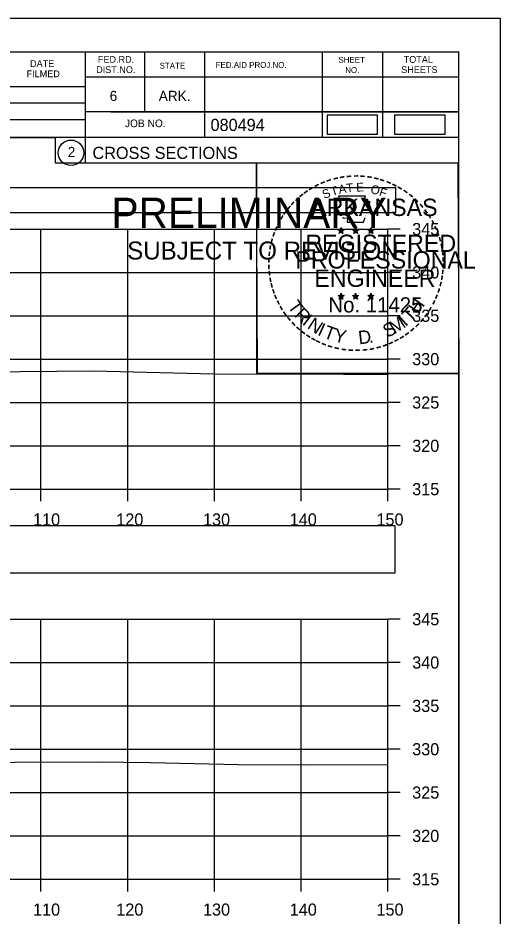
# Model space of a CAD drawing. Extents: x 1376273 to 1384221, y 378927 to 384592.
# Drawn here: x 1380299 to 1380354.6, y 384275 to 384378.6 of the extents above; entities that cross this region are included whole.
import ezdxf

# ---------------------------------------------------------------- set-up
doc = ezdxf.new("R2010")
doc.units = 0
for name, color, linetype in [('R_Axis', 7, 'Continuous'), ('R_Axis Annot', 7, 'Continuous'), ('R_Border', 7, 'Continuous'), ('R_Border PE', 7, 'Continuous'), ('R_Border Prem', 7, 'Continuous'), ('R_Drive', 7, 'Continuous'), ('R_Exist Surface', 7, 'Continuous'), ('R_Grid', 7, 'Continuous'), ('R_No Plot', 7, 'Continuous')]:
    doc.layers.add(name, color=color, linetype=linetype)

msp = doc.modelspace()

# ---------------------------------------------------------------- linework, layer by layer
at = {"layer": 'R_Axis'}
for p, q in [((1380341.66, 384324.24), (1380341.66, 384354.24)), ((1380343.06, 384354.24), (1380341.66, 384354.24)), ((1380343.06, 384349.24), (1380341.66, 384349.24)), ((1380343.06, 384344.24), (1380341.66, 384344.24)), ((1380343.06, 384339.24), (1380341.66, 384339.24)), ((1380343.06, 384334.24), (1380341.66, 384334.24)), ((1380343.06, 384329.24), (1380341.66, 384329.24)), ((1380041.66, 384324.24), (1380341.66, 384324.24)), ((1380301.66, 384322.84), (1380301.66, 384324.24)), ((1380311.66, 384322.84), (1380311.66, 384324.24)), ((1380321.66, 384322.84), (1380321.66, 384324.24)), ((1380331.66, 384322.84), (1380331.66, 384324.24)), ((1380341.66, 384322.84), (1380341.66, 384324.24)), ((1380343.06, 384324.24), (1380341.66, 384324.24)), ((1380341.66, 384279.24), (1380341.66, 384309.24)), ((1380343.06, 384309.24), (1380341.66, 384309.24)), ((1380343.06, 384304.24), (1380341.66, 384304.24)), ((1380343.06, 384299.24), (1380341.66, 384299.24)), ((1380343.06, 384294.24), (1380341.66, 384294.24)), ((1380343.06, 384289.24), (1380341.66, 384289.24)), ((1380343.06, 384284.24), (1380341.66, 384284.24)), ((1380041.66, 384279.24), (1380341.66, 384279.24)), ((1380301.66, 384277.84), (1380301.66, 384279.24)), ((1380311.66, 384277.84), (1380311.66, 384279.24)), ((1380321.66, 384277.84), (1380321.66, 384279.24)), ((1380331.66, 384277.84), (1380331.66, 384279.24)), ((1380341.66, 384277.84), (1380341.66, 384279.24)), ((1380343.06, 384279.24), (1380341.66, 384279.24))]:
    msp.add_line(p, q, dxfattribs=at)
at = {"layer": 'R_Axis Annot'}
for points in [[(1380040.77, 384356.17), (1380342.57, 384356.17), (1380342.57, 384358.98), (1380040.77, 384358.98)], [(1380040.81, 384314.59), (1380342.5, 384314.59), (1380342.5, 384320), (1380040.81, 384320)]]:
    msp.add_lwpolyline(points, close=True, dxfattribs=at)
at = {"layer": 'R_Border'}
for p, q in [((1380033.66, 384374.7), (1380349.84, 384374.7)), ((1380306.74, 384374.7), (1380306.74, 384361.9)), ((1380313.58, 384374.7), (1380313.58, 384367.76)), ((1380320.52, 384374.7), (1380320.52, 384364.82)), ((1380334.1, 384374.7), (1380334.1, 384364.82)), ((1380341.04, 384374.7), (1380341.04, 384364.82)), ((1380349.84, 384169.24), (1380349.84, 384374.7)), ((1380349.84, 384371.76), (1380306.74, 384371.76)), ((1380349.84, 384371.78), (1380349.84, 384371.78)), ((1380267.58, 384370.68), (1380306.74, 384370.68)), ((1380267.58, 384368.82), (1380306.74, 384368.82)), ((1380349.84, 384367.76), (1380306.74, 384367.76)), ((1380309.7, 384367.76), (1380349.84, 384367.76)), ((1380267.58, 384366.88), (1380306.74, 384366.88)), ((1380349.84, 384364.82), (1380267.58, 384364.82)), ((1380306.74, 384361.9), (1380349.84, 384361.9))]:
    msp.add_line(p, q, dxfattribs=at)
msp.add_circle((1380305.12, 384363.04), 1.47, dxfattribs=at)
at = {"layer": 'R_Border PE'}
for p, q in [((1380335.92, 384354.16), (1380336.27, 384354.04)), ((1380335.92, 384354.16), (1380336.18, 384354.11)), ((1380335.92, 384354.16), (1380336.16, 384354.03)), ((1380336.06, 384353.75), (1380336.27, 384354.04)), ((1380336.06, 384353.75), (1380336.18, 384353.99)), ((1380336.06, 384353.75), (1380336.27, 384353.96)), ((1380336.27, 384354.41), (1380336.23, 384354.16)), ((1380336.27, 384354.04), (1380336.27, 384354.41)), ((1380336.27, 384354.41), (1380336.32, 384354.16)), ((1380336.62, 384354.16), (1380336.27, 384354.04)), ((1380336.48, 384353.75), (1380336.27, 384354.04)), ((1380336.48, 384353.75), (1380336.27, 384353.96)), ((1380336.62, 384354.16), (1380336.33, 384354.11)), ((1380336.48, 384353.75), (1380336.35, 384354.04)), ((1380336.62, 384354.16), (1380336.41, 384354.05)), ((1380337.59, 384354.16), (1380337.94, 384354.04)), ((1380337.59, 384354.16), (1380337.85, 384354.11)), ((1380337.59, 384354.16), (1380337.83, 384354.03)), ((1380337.73, 384353.75), (1380337.94, 384354.04)), ((1380337.73, 384353.75), (1380337.85, 384353.99)), ((1380337.73, 384353.75), (1380337.94, 384353.96)), ((1380337.94, 384354.41), (1380337.9, 384354.16)), ((1380337.94, 384354.04), (1380337.94, 384354.41)), ((1380337.94, 384354.41), (1380337.99, 384354.16)), ((1380338.29, 384354.16), (1380337.94, 384354.04)), ((1380338.15, 384353.75), (1380337.94, 384354.04)), ((1380338.15, 384353.75), (1380337.94, 384353.96)), ((1380338.29, 384354.16), (1380338, 384354.11)), ((1380338.15, 384353.75), (1380338.02, 384354.04)), ((1380338.29, 384354.16), (1380338.08, 384354.05)), ((1380339.36, 384354.14), (1380339.71, 384354.03)), ((1380339.36, 384354.14), (1380339.61, 384354.1)), ((1380339.36, 384354.14), (1380339.59, 384354.02)), ((1380339.49, 384353.74), (1380339.71, 384354.03)), ((1380339.49, 384353.74), (1380339.62, 384353.98)), ((1380339.49, 384353.74), (1380339.7, 384353.95)), ((1380339.71, 384354.4), (1380339.66, 384354.15)), ((1380339.92, 384353.74), (1380339.7, 384353.95)), ((1380339.71, 384354.03), (1380339.71, 384354.4)), ((1380339.71, 384354.4), (1380339.75, 384354.15)), ((1380340.05, 384354.14), (1380339.71, 384354.03)), ((1380339.92, 384353.74), (1380339.71, 384354.03)), ((1380340.05, 384354.14), (1380339.77, 384354.09)), ((1380339.92, 384353.74), (1380339.78, 384354.03)), ((1380340.05, 384354.14), (1380339.85, 384354.04)), ((1380336.27, 384346.84), (1380336.23, 384346.58)), ((1380336.27, 384346.47), (1380336.27, 384346.84)), ((1380336.27, 384346.84), (1380336.32, 384346.59)), ((1380337.94, 384346.84), (1380337.9, 384346.58)), ((1380337.94, 384346.47), (1380337.94, 384346.84)), ((1380337.94, 384346.84), (1380337.99, 384346.59)), ((1380339.7, 384346.83), (1380339.66, 384346.57)), ((1380339.7, 384346.46), (1380339.7, 384346.83)), ((1380339.7, 384346.83), (1380339.75, 384346.58)), ((1380335.92, 384346.58), (1380336.27, 384346.47)), ((1380335.92, 384346.58), (1380336.17, 384346.54)), ((1380335.92, 384346.58), (1380336.16, 384346.46)), ((1380336.05, 384346.17), (1380336.27, 384346.47)), ((1380336.05, 384346.17), (1380336.18, 384346.42)), ((1380336.05, 384346.17), (1380336.27, 384346.39)), ((1380336.61, 384346.58), (1380336.27, 384346.47)), ((1380336.48, 384346.17), (1380336.27, 384346.47)), ((1380336.48, 384346.17), (1380336.27, 384346.39)), ((1380336.61, 384346.58), (1380336.33, 384346.53)), ((1380336.48, 384346.17), (1380336.34, 384346.47)), ((1380336.61, 384346.58), (1380336.41, 384346.48)), ((1380337.59, 384346.58), (1380337.94, 384346.47)), ((1380337.59, 384346.58), (1380337.84, 384346.54)), ((1380337.59, 384346.58), (1380337.82, 384346.46)), ((1380337.72, 384346.17), (1380337.94, 384346.47)), ((1380337.72, 384346.17), (1380337.85, 384346.42)), ((1380337.72, 384346.17), (1380337.93, 384346.39)), ((1380338.15, 384346.17), (1380337.93, 384346.39)), ((1380338.28, 384346.58), (1380337.94, 384346.47)), ((1380338.15, 384346.17), (1380337.94, 384346.47)), ((1380338.28, 384346.58), (1380338, 384346.53)), ((1380338.15, 384346.17), (1380338.01, 384346.47)), ((1380338.28, 384346.58), (1380338.08, 384346.48)), ((1380339.35, 384346.57), (1380339.7, 384346.46)), ((1380339.35, 384346.57), (1380339.61, 384346.53)), ((1380339.35, 384346.57), (1380339.59, 384346.45)), ((1380339.49, 384346.16), (1380339.7, 384346.46)), ((1380339.49, 384346.16), (1380339.61, 384346.41)), ((1380339.49, 384346.16), (1380339.7, 384346.38)), ((1380340.05, 384346.57), (1380339.7, 384346.46)), ((1380339.92, 384346.16), (1380339.7, 384346.46)), ((1380339.92, 384346.16), (1380339.7, 384346.38)), ((1380340.05, 384346.57), (1380339.76, 384346.52)), ((1380339.92, 384346.16), (1380339.78, 384346.46)), ((1380340.05, 384346.57), (1380339.85, 384346.47))]:
    msp.add_line(p, q, dxfattribs=at)
for points in [[(1380335.96, 384358.03), (1380336.23, 384357.21)], [(1380339.47, 384357.11), (1380339.62, 384357.4), (1380338.93, 384357.37), (1380339.08, 384358.03), (1380335.96, 384358.03)], [(1380336.46, 384355.61), (1380336.46, 384355.52), (1380337.02, 384355.5), (1380336.96, 384355.03), (1380338.83, 384355.03), (1380339.04, 384355.57)], [(1380336.27, 384354.41), (1380336.48, 384353.75), (1380335.92, 384354.16), (1380336.62, 384354.16), (1380336.06, 384353.75), (1380336.27, 384354.41)], [(1380337.94, 384354.41), (1380338.15, 384353.75), (1380337.59, 384354.16), (1380338.29, 384354.16), (1380337.73, 384353.75), (1380337.94, 384354.41)], [(1380339.71, 384354.4), (1380339.92, 384353.74), (1380339.36, 384354.14), (1380340.05, 384354.14), (1380339.49, 384353.74), (1380339.71, 384354.4)], [(1380336.27, 384346.84), (1380336.48, 384346.17), (1380335.92, 384346.58), (1380336.61, 384346.58), (1380336.05, 384346.17), (1380336.27, 384346.84)], [(1380337.94, 384346.84), (1380338.15, 384346.17), (1380337.59, 384346.58), (1380338.28, 384346.58), (1380337.72, 384346.17), (1380337.94, 384346.84)], [(1380339.7, 384346.83), (1380339.92, 384346.16), (1380339.35, 384346.57), (1380340.05, 384346.57), (1380339.49, 384346.16), (1380339.7, 384346.83)]]:
    msp.add_lwpolyline(points, dxfattribs=at)
for centre, radius in [((1380336.27, 384354.04), 0.172), ((1380336.27, 384354.04), 0.145), ((1380336.27, 384354.04), 0.116), ((1380336.27, 384354.04), 0.0991), ((1380336.27, 384354.04), 0.0747), ((1380336.27, 384354.04), 0.0495), ((1380336.27, 384354.04), 0.0296), ((1380337.94, 384354.04), 0.172), ((1380337.94, 384354.04), 0.145), ((1380337.94, 384354.04), 0.116), ((1380337.94, 384354.04), 0.0991), ((1380337.94, 384354.04), 0.0747), ((1380337.94, 384354.04), 0.0495), ((1380337.94, 384354.04), 0.0296), ((1380339.7, 384354.03), 0.172), ((1380339.7, 384354.03), 0.145), ((1380339.7, 384354.03), 0.116), ((1380339.7, 384354.03), 0.0991), ((1380339.7, 384354.03), 0.0747), ((1380339.7, 384354.03), 0.0495), ((1380339.7, 384354.03), 0.0296), ((1380336.27, 384346.47), 0.172), ((1380336.27, 384346.47), 0.145), ((1380336.27, 384346.47), 0.116), ((1380336.27, 384346.47), 0.0991), ((1380336.27, 384346.47), 0.0747), ((1380336.27, 384346.47), 0.0495), ((1380336.27, 384346.47), 0.0296), ((1380337.94, 384346.47), 0.172), ((1380337.94, 384346.47), 0.145), ((1380337.94, 384346.47), 0.116), ((1380337.94, 384346.47), 0.0991), ((1380337.94, 384346.47), 0.0747), ((1380337.94, 384346.47), 0.0495), ((1380337.94, 384346.47), 0.0296), ((1380339.7, 384346.46), 0.172), ((1380339.7, 384346.46), 0.145), ((1380339.7, 384346.46), 0.116), ((1380339.7, 384346.46), 0.0991), ((1380339.7, 384346.46), 0.0747), ((1380339.7, 384346.46), 0.0495), ((1380339.7, 384346.46), 0.0296)]:
    msp.add_circle(centre, radius, dxfattribs=at)
at = {"layer": 'R_Drive'}
for points in [[(1380334.64, 384365.2), (1380340.47, 384365.2), (1380340.47, 384367.38), (1380334.64, 384367.38)], [(1380342.44, 384365.2), (1380348.28, 384365.2), (1380348.28, 384367.39), (1380342.44, 384367.39)]]:
    msp.add_lwpolyline(points, close=True, dxfattribs=at)
at = {"layer": 'R_Exist Surface'}
for points in [[(1380236.61, 384338.19), (1380249.35, 384337.74), (1380250.65, 384337.7), (1380253.32, 384337.71), (1380271, 384337.83), (1380287.86, 384337.75), (1380293.77, 384337.73), (1380299.24, 384337.81), (1380307.71, 384337.9), (1380313.87, 384337.75), (1380321.58, 384337.55), (1380336.54, 384337.52), (1380341.66, 384337.51)], [(1380246.67, 384292.78), (1380250.92, 384292.63), (1380270.06, 384292.82), (1380271.33, 384292.83), (1380272.92, 384292.83), (1380293.38, 384292.71), (1380298.65, 384292.75), (1380308.15, 384292.8), (1380314.27, 384292.69), (1380324.43, 384292.47), (1380332.71, 384292.45), (1380341.66, 384292.48)]]:
    msp.add_lwpolyline(points, dxfattribs=at)
at = {"layer": 'R_Grid'}
for p, q in [((1380041.66, 384354.24), (1380341.66, 384354.24)), ((1380301.66, 384324.24), (1380301.66, 384354.24)), ((1380311.66, 384324.24), (1380311.66, 384354.24)), ((1380321.66, 384324.24), (1380321.66, 384354.24)), ((1380331.66, 384324.24), (1380331.66, 384354.24)), ((1380341.66, 384324.24), (1380341.66, 384354.24)), ((1380041.66, 384349.24), (1380341.66, 384349.24)), ((1380041.66, 384344.24), (1380341.66, 384344.24)), ((1380041.66, 384339.24), (1380341.66, 384339.24)), ((1380041.66, 384334.24), (1380341.66, 384334.24)), ((1380041.66, 384329.24), (1380341.66, 384329.24)), ((1380041.66, 384324.24), (1380341.66, 384324.24)), ((1380041.66, 384309.24), (1380341.66, 384309.24)), ((1380301.66, 384279.24), (1380301.66, 384309.24)), ((1380311.66, 384279.24), (1380311.66, 384309.24)), ((1380321.66, 384279.24), (1380321.66, 384309.24)), ((1380331.66, 384279.24), (1380331.66, 384309.24)), ((1380341.66, 384279.24), (1380341.66, 384309.24)), ((1380041.66, 384304.24), (1380341.66, 384304.24)), ((1380041.66, 384299.24), (1380341.66, 384299.24)), ((1380041.66, 384294.24), (1380341.66, 384294.24)), ((1380041.66, 384289.24), (1380341.66, 384289.24)), ((1380041.66, 384284.24), (1380341.66, 384284.24)), ((1380041.66, 384279.24), (1380341.66, 384279.24))]:
    msp.add_line(p, q, dxfattribs=at)
at = {"layer": 'R_No Plot'}
for p, q in [((1380021.26, 384378.59), (1380354.59, 384378.59)), ((1380325.87, 384339.44), (1380325.87, 384339.44))]:
    msp.add_line(p, q, dxfattribs=at)
for points in [[(1380021.25, 384378.59), (1380354.59, 384378.59), (1380354.59, 384165.26), (1380021.25, 384165.26)], [(1380267.58, 384374.7), (1380267.58, 384364.82), (1380303.31, 384364.82), (1380303.31, 384361.9), (1380326.51, 384361.9), (1380326.51, 384337.57), (1380349.84, 384337.57), (1380349.84, 384169.24), (1380033.66, 384169.24), (1380033.66, 384374.7)], [(1380326.51, 384361.9), (1380349.72, 384361.9), (1380349.84, 384337.57), (1380326.63, 384337.57)]]:
    msp.add_lwpolyline(points, close=True, dxfattribs=at)

# ---------------------------------------------------------------- texts
at = {"layer": 'R_Axis Annot'}
for s, p in [('345', (1380344.46, 384353.54)), ('340', (1380344.46, 384348.54)), ('335', (1380344.46, 384343.54)), ('330', (1380344.46, 384338.54)), ('325', (1380344.46, 384333.54)), ('320', (1380344.46, 384328.54)), ('315', (1380344.46, 384323.54)), ('110', (1380300.74, 384320.04)), ('120', (1380310.34, 384320.04)), ('130', (1380320.34, 384320.04)), ('140', (1380330.34, 384320.04)), ('150', (1380340.34, 384320.04)), ('345', (1380344.46, 384308.54)), ('340', (1380344.46, 384303.54)), ('335', (1380344.46, 384298.54)), ('330', (1380344.46, 384293.54)), ('325', (1380344.46, 384288.54)), ('320', (1380344.46, 384283.54)), ('315', (1380344.46, 384278.54)), ('110', (1380300.74, 384275.04)), ('120', (1380310.34, 384275.04)), ('130', (1380320.34, 384275.04)), ('140', (1380330.34, 384275.04)), ('150', (1380340.34, 384275.04))]:
    msp.add_text(s, height=1.4, dxfattribs=at).set_placement(p)
at = {"layer": 'R_Border'}
for s, height, p in [('DATE', 0.782, (1380300.4, 384372.94)), ('FED.RD.', 0.782, (1380308.22, 384373.42)), ('SHEET', 0.684, (1380335.96, 384373.42)), ('TOTAL', 0.782, (1380343.48, 384373.42)), ('DIST.NO.', 0.782, (1380308.02, 384372.24)), ('STATE', 0.684, (1380315.34, 384372.74)), ('FED.AID PROJ.NO.', 0.684, (1380321.8, 384372.84)), ('NO.', 0.684, (1380336.74, 384372.24)), ('SHEETS', 0.782, (1380343.2, 384372.24)), ('FILMED', 0.782, (1380300, 384371.76)), ('6', 1.17, (1380309.58, 384369.02)), ('ARK.', 1.172, (1380315.24, 384369.02)), ('JOB NO.', 0.879, (1380311.34, 384366)), ('080494', 1.4, (1380321.21, 384365.56)), ('2', 1.17, (1380304.74, 384362.55)), ('CROSS SECTIONS', 1.4, (1380307.6, 384362.33))]:
    msp.add_text(s, height=height, rotation=360, dxfattribs=at).set_placement(p)
at = {"layer": 'R_Border PE'}
for s, height, rotation, p in [('-', 1.6, 13.6301, (1380335.46, 384359.4)), ('-', 1.6, 10.2193, (1380336.14, 384359.56)), ('-', 1.6, 5.8968, (1380336.87, 384359.67)), ('-', 1.6, 0.1862, (1380337.64, 384359.75)), ('-', 1.6, 357.743, (1380338.36, 384359.73)), ('-', 1.6, 352.1617, (1380339.11, 384359.68)), ('-', 1.6, 347.2049, (1380339.83, 384359.56)), ('-', 1.6, 34.0636, (1380332.85, 384358.2)), ('-', 1.6, 28.7918, (1380333.44, 384358.57)), ('-', 1.6, 24.3072, (1380334.08, 384358.89)), ('-', 1.6, 19.1761, (1380334.71, 384359.16)), ('T', 1, 16.4036, (1380335.23, 384358.04)), ('A', 1, 11.2132, (1380336.06, 384358.29)), ('T', 1, 6.0228, (1380336.91, 384358.46)), ('E', 1, 0.8323, (1380338.01, 384358.57)), ('O', 1, 350.4515, (1380339.62, 384358.36)), ('-', 1.6, 342.3362, (1380340.46, 384359.41)), ('-', 1.6, 337.8551, (1380341.2, 384359.18)), ('-', 1.6, 334.1211, (1380341.83, 384358.91)), ('-', 1.6, 329.6409, (1380342.41, 384358.63)), ('-', 1.6, 38.9507, (1380331.79, 384357.43)), ('-', 1.6, 36.2317, (1380332.27, 384357.81)), ('S', 1, 21.594, (1380334.32, 384357.71)), ('F', 1, 340.0707, (1380340.57, 384358.13)), ('-', 1.6, 325.8627, (1380343.05, 384358.27)), ('-', 1.6, 320.5297, (1380343.66, 384357.84)), ('-', 1.6, 48.423, (1380330.91, 384356.54)), ('-', 1.6, 42.9622, (1380331.36, 384357.01)), ('ARKANSAS', 2, 360, (1380332.82, 384355.75)), ('-', 1.6, 315.5786, (1380344.26, 384357.36)), ('-', 1.6, 309.8797, (1380344.83, 384356.81)), ('-', 1.6, 54.2325, (1380330.1, 384355.48)), ('-', 1.6, 50.6142, (1380330.51, 384356.05)), ('-', 1.6, 306.6522, (1380345.35, 384356.2)), ('-', 1.6, 62.8713, (1380329.46, 384354.34)), ('-', 1.6, 58.0706, (1380329.77, 384354.96)), ('-', 1.4, 303.6753, (1380345.84, 384355.64)), ('-', 1.6, 299.6684, (1380346.16, 384355.03)), ('-', 1.6, 72.3945, (1380328.98, 384353.1)), ('-', 1.6, 67.7743, (1380329.2, 384353.73)), ('DWB', 0.01, 360, (1380336.26, 384354.04)), ('DWB', 0.01, 360, (1380337.93, 384354.04)), ('DWB', 0.01, 360, (1380339.69, 384354.03)), ('-', 1.6, 294.6628, (1380346.48, 384354.42)), ('-', 1.6, 290.5728, (1380346.74, 384353.84)), ('-', 1.6, 75.461, (1380328.78, 384352.39)), ('REGISTERED', 2, 360, (1380332.14, 384351.6)), ('-', 1.6, 285.1233, (1380346.97, 384353.26)), ('-', 1.6, 81.2013, (1380328.65, 384351.67)), ('-', 1.6, 280.5493, (1380347.17, 384352.52)), ('-', 1.6, 89.0622, (1380328.55, 384350.28)), ('-', 1.6, 85.1863, (1380328.57, 384350.98)), ('PROFESSIONAL', 2, 360, (1380330.99, 384349.69)), ('-', 1.6, 276.5962, (1380347.33, 384351.75)), ('-', 1.6, 274.3301, (1380347.39, 384351.03)), ('-', 1.6, 94.1959, (1380328.58, 384349.56)), ('-', 1.6, 269.9407, (1380347.43, 384350.4)), ('-', 1.6, 98.9479, (1380328.66, 384348.89)), ('ENGINEER', 2, 360, (1380333.18, 384347.57)), ('-', 1.6, 260.9953, (1380347.34, 384349.08)), ('-', 1.6, 263.5172, (1380347.41, 384349.73)), ('-', 1.6, 101.7149, (1380328.79, 384348.16)), ('-', 1.6, 105.4578, (1380328.95, 384347.56)), ('-', 1.6, 255.7626, (1380347.23, 384348.4)), ('-', 1.6, 109.0874, (1380329.17, 384346.93)), ('-', 1.6, 114.0643, (1380329.42, 384346.34)), ('-', 1.6, 247.8887, (1380346.82, 384347)), ('-', 1.6, 252.8681, (1380347.05, 384347.68)), ('-', 1.6, 115.7289, (1380329.73, 384345.72)), ('T', 1.54, 306.0406, (1380330.03, 384345.31)), ('No. 11425', 1.757, 360, (1380334.8, 384344.62)), ('DWB', 0.01, 360, (1380336.25, 384346.47)), ('DWB', 0.01, 360, (1380337.92, 384346.47)), ('DWB', 0.01, 360, (1380339.69, 384346.46)), ('H', 1.54, 54.6088, (1380345.15, 384344.34)), ('-', 1.6, 244.6197, (1380346.56, 384346.38)), ('-', 1.6, 120.4471, (1380330.08, 384345.13)), ('-', 1.6, 125.8934, (1380330.49, 384344.57)), ('R', 1.54, 314.005, (1380330.79, 384344.26)), ('T', 1.54, 46.6444, (1380344.26, 384343.4)), ('-', 1.6, 233.8452, (1380345.77, 384344.97)), ('-', 1.6, 239.0712, (1380346.17, 384345.62)), ('-', 1.6, 130.7181, (1380330.95, 384344.02)), ('-', 1.6, 134.2238, (1380331.47, 384343.47)), ('I', 1.54, 321.9694, (1380331.69, 384343.33)), ('N', 1.54, 326.5002, (1380332.26, 384342.86)), ('M', 1.54, 32.6563, (1380342.41, 384342.08)), ('I', 1.54, 42.1136, (1380343.7, 384342.92)), ('-', 1.6, 231.2538, (1380345.34, 384344.4)), ('-', 1.6, 138.9338, (1380331.99, 384343.01)), ('-', 1.6, 144.6463, (1380332.55, 384342.6)), ('I', 1.54, 335.3603, (1380333.46, 384342.07)), ('T', 1.54, 339.8912, (1380334.13, 384341.74)), ('Y', 1.54, 347.8556, (1380335.34, 384341.3)), ('D', 1.54, 6.3969, (1380338.33, 384340.94)), ('S', 1.54, 26.9312, (1380341.57, 384341.67)), ('-', 1.6, 221.0851, (1380344.33, 384343.33)), ('-', 1.6, 225.7653, (1380344.86, 384343.84)), ('-', 1.6, 148.0898, (1380333.11, 384342.23)), ('-', 1.6, 151.5704, (1380333.69, 384341.91)), ('-', 1.6, 207.3568, (1380342.69, 384342.13)), ('-', 1.6, 212.2491, (1380343.25, 384342.47)), ('-', 1.6, 215.7363, (1380343.79, 384342.86)), ('-', 1.6, 154.6002, (1380334.21, 384341.66)), ('-', 1.6, 158.5612, (1380334.83, 384341.41)), ('-', 1.6, 162.7983, (1380335.52, 384341.19)), ('-', 1.6, 167.5555, (1380336.24, 384341.03)), ('-', 1.6, 173.1155, (1380337.01, 384340.92)), ('-', 1.6, 185.8167, (1380339.31, 384340.96)), ('-', 1.6, 191.2858, (1380340.04, 384341.09)), ('.', 1.54, 13.7642, (1380339.52, 384341.07)), ('-', 1.6, 195.4743, (1380340.77, 384341.29)), ('-', 1.6, 200.7184, (1380341.45, 384341.53)), ('-', 1.6, 204.2516, (1380342.07, 384341.81)), ('-', 1.6, 176.5183, (1380337.76, 384340.87)), ('-', 1.6, 181.5918, (1380338.5, 384340.89))]:
    msp.add_text(s, height=height, rotation=rotation, dxfattribs=at).set_placement(p)
at = {"layer": 'R_Border Prem'}
for s, height, p in [('PRELIMINARY', 3.5, (1380309.79, 384354.36)), ('DWB', 0.01, (1380310.53, 384356.21)), ('SUBJECT TO REVISION', 2.0751, (1380311.6, 384350.73))]:
    msp.add_text(s, height=height, rotation=360, dxfattribs=at).set_placement(p)

doc.saveas('drawing.dxf')
